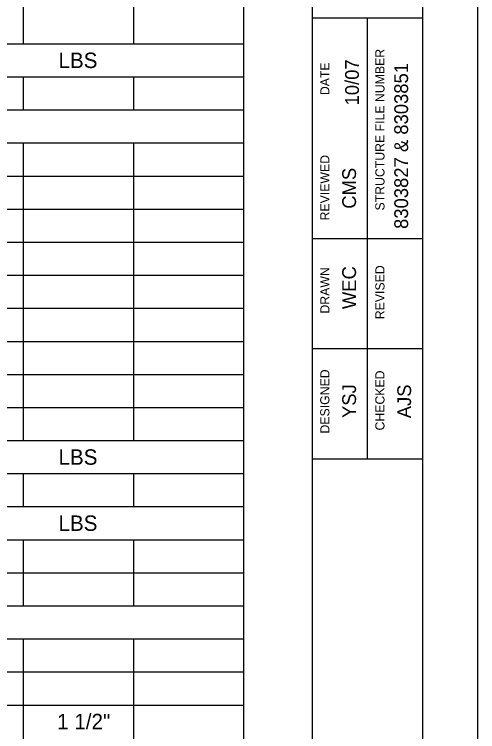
# Model space of a CAD drawing. Extents: x 1485751 to 1485785, y 230696.6 to 230718.6.
# Drawn here: x 1485780.83 to 1485785.03, y 230708.16 to 230714.67 of the extents above; entities that cross this region are included whole.
import ezdxf

# ---------------------------------------------------------------- set-up
doc = ezdxf.new("R2010")
doc.units = 0
for name, color, linetype in [('SH_Border', 7, 'Continuous'), ('SH_Cut_Line', 7, 'Continuous'), ('SH_Data', 7, 'Continuous'), ('TX_P_Misc', 7, 'Continuous')]:
    doc.layers.add(name, color=color, linetype=linetype)

msp = doc.modelspace()

# ---------------------------------------------------------------- linework, layer by layer
at = {"layer": 'SH_Border'}
for p, q in [((1485783.5329, 230697.1408), (1485783.5329, 230718.1408)), ((1485783.5329, 230697.1408), (1485783.5329, 230718.1408)), ((1485783.5329, 230697.1408), (1485783.5329, 230718.1408)), ((1485783.5329, 230714.6408), (1485784.5329, 230714.6408)), ((1485783.5329, 230714.6408), (1485784.5329, 230714.6408)), ((1485783.5329, 230714.6408), (1485784.5329, 230714.6408)), ((1485784.0329, 230710.6408), (1485784.0329, 230714.6408)), ((1485784.0329, 230710.6408), (1485784.0329, 230714.6408)), ((1485784.0329, 230710.6408), (1485784.0329, 230714.6408)), ((1485783.5329, 230712.6408), (1485784.5329, 230712.6408)), ((1485783.5329, 230712.6408), (1485784.5329, 230712.6408)), ((1485783.5329, 230712.6408), (1485784.5329, 230712.6408)), ((1485783.5329, 230711.6408), (1485784.5329, 230711.6408)), ((1485783.5329, 230711.6408), (1485784.5329, 230711.6408)), ((1485783.5329, 230711.6408), (1485784.5329, 230711.6408)), ((1485783.5329, 230710.6408), (1485784.5329, 230710.6408)), ((1485783.5329, 230710.6408), (1485784.5329, 230710.6408)), ((1485783.5329, 230710.6408), (1485784.5329, 230710.6408))]:
    msp.add_line(p, q, dxfattribs=at)
msp.add_lwpolyline([(1485753.0329, 230718.1408), (1485784.5329, 230718.1408), (1485784.5329, 230697.1408), (1485753.0329, 230697.1408)], close=True, dxfattribs=at)
at = {"layer": 'SH_Cut_Line'}
msp.add_lwpolyline([(1485751.0329, 230718.6408), (1485785.0329, 230718.6408), (1485785.0329, 230696.6408), (1485751.0329, 230696.6408)], close=True, dxfattribs=at)
at = {"layer": 'TX_P_Misc'}
for p, q in [((1485780.9079, 230716.9565), (1485780.9079, 230714.4065)), ((1485781.9079, 230716.9565), (1485781.9079, 230714.4065)), ((1485782.9079, 230716.9565), (1485782.9079, 230702.4065)), ((1485773.6579, 230714.4065), (1485782.9079, 230714.4065)), ((1485773.6579, 230714.1065), (1485782.9079, 230714.1065)), ((1485780.9079, 230714.1065), (1485780.9079, 230713.8065)), ((1485781.9079, 230714.1065), (1485781.9079, 230713.8065)), ((1485773.6579, 230713.8065), (1485782.9079, 230713.8065)), ((1485773.6579, 230713.5065), (1485782.9079, 230713.5065)), ((1485780.9079, 230713.5065), (1485780.9079, 230710.8065)), ((1485781.9079, 230713.5065), (1485781.9079, 230710.8065)), ((1485773.6579, 230713.2065), (1485782.9079, 230713.2065)), ((1485773.6579, 230712.9065), (1485782.9079, 230712.9065)), ((1485773.6579, 230712.6065), (1485782.9079, 230712.6065)), ((1485773.6579, 230712.3065), (1485782.9079, 230712.3065)), ((1485773.6579, 230712.0065), (1485782.9079, 230712.0065)), ((1485773.6579, 230711.7065), (1485782.9079, 230711.7065)), ((1485773.6579, 230711.4065), (1485782.9079, 230711.4065)), ((1485773.6579, 230711.1065), (1485782.9079, 230711.1065)), ((1485773.6579, 230710.8065), (1485782.9079, 230710.8065)), ((1485773.6579, 230710.5065), (1485782.9079, 230710.5065)), ((1485780.9079, 230710.5065), (1485780.9079, 230710.2065)), ((1485781.9079, 230710.5065), (1485781.9079, 230710.2065)), ((1485773.6579, 230710.2065), (1485782.9079, 230710.2065)), ((1485773.6579, 230709.9065), (1485782.9079, 230709.9065)), ((1485780.9079, 230709.9065), (1485780.9079, 230709.3065)), ((1485781.9079, 230709.9065), (1485781.9079, 230709.3065)), ((1485773.6579, 230709.6065), (1485782.9079, 230709.6065)), ((1485773.6579, 230709.3065), (1485782.9079, 230709.3065)), ((1485773.6579, 230709.0065), (1485782.9079, 230709.0065)), ((1485780.9079, 230709.0065), (1485780.9079, 230703.6065)), ((1485781.9079, 230709.0065), (1485781.9079, 230703.6065)), ((1485773.6579, 230708.7065), (1485782.9079, 230708.7065)), ((1485773.6579, 230708.4065), (1485782.9079, 230708.4065))]:
    msp.add_line(p, q, dxfattribs=at)

# ---------------------------------------------------------------- texts
at = {"layer": 'SH_Data'}
for s, height, p in [('STRUCTURE FILE NUMBER', 0.0833, (1485784.187, 230712.8938)), ('10/07', 0.125, (1485783.9549, 230713.8469)), ('DATE', 0.0833, (1485783.687, 230713.9405)), ('8303827 & 8303851', 0.125, (1485784.4012, 230712.7264)), ('REVIEWED', 0.0833, (1485783.687, 230712.8035)), ('CMS', 0.125, (1485783.9287, 230712.9095)), ('DRAWN', 0.0833, (1485783.687, 230711.9585)), ('WEC', 0.125, (1485783.9287, 230711.9985)), ('REVISED', 0.0833, (1485784.187, 230711.9073)), ('DESIGNED', 0.0833, (1485783.687, 230710.87)), ('CHECKED', 0.0833, (1485784.187, 230710.8975)), ('AJS', 0.125, (1485784.4287, 230711.0083)), ('YSJ', 0.125, (1485783.9287, 230711.0108))]:
    msp.add_text(s, height=height, rotation=90, dxfattribs=at).set_placement(p)
at = {"layer": 'TX_P_Misc'}
for s, p in [('LBS', (1485781.2276, 230714.1865)), ('LBS', (1485781.2276, 230710.5865)), ('LBS', (1485781.2276, 230709.9865)), (' 1 1/2"', (1485781.1632, 230708.1865))]:
    msp.add_text(s, height=0.14, dxfattribs=at).set_placement(p)

doc.saveas('drawing.dxf')
